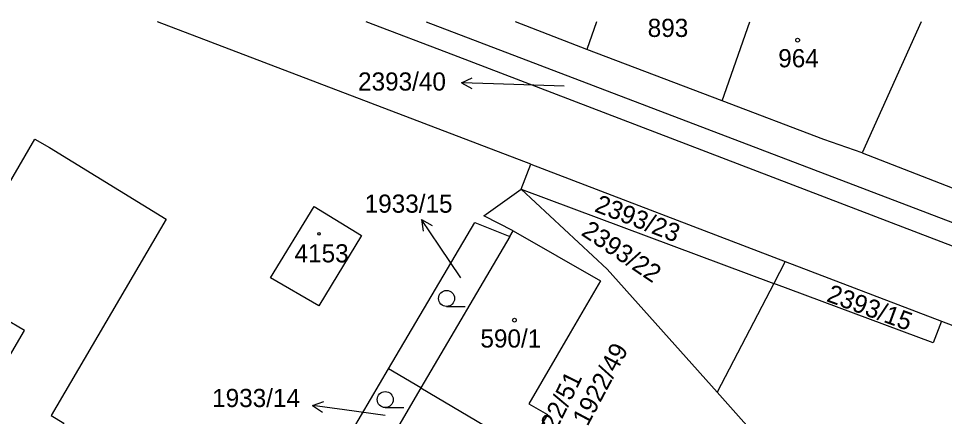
# Model space of a CAD drawing. Extents: x -667048 to -665920, y -1108425 to -1107247.
# Drawn here: x -666872 to -666785.4, y -1107285.9 to -1107248.7 of the extents above; entities that cross this region are included whole.
import ezdxf

# ---------------------------------------------------------------- set-up
doc = ezdxf.new("R2010")
doc.units = 0
for name, color, linetype in [('Default', 7, 'Continuous'), ('Hranice parcel', 7, 'Continuous'), ('Parcelní čísla', 7, 'Continuous'), ('Pop_ PČ_ popisy', 7, 'Continuous'), ('Značky budov', 7, 'Continuous'), ('Značky kultur', 7, 'Continuous')]:
    doc.layers.add(name, color=color, linetype=linetype)

# ---------------------------------------------------------------- blocks, each defined once
blk = doc.blocks.new('3.041')
at = {"layer": 'Default'}
blk.add_line((8, 0), (1758, 0), dxfattribs=at)
blk.add_circle((8, 750), 750, dxfattribs=at)
blk = doc.blocks.new('4.021')
at = {"layer": 'Default'}
blk.add_circle((-7, 1), 175, dxfattribs=at)
blk = doc.blocks.new('10291')
at = {"layer": 'Default'}
for p, q in [((0, 3001), (-500, 2001)), ((0, 1), (0, 3001)), ((0, 3001), (500, 2001))]:
    blk.add_line(p, q, dxfattribs=at)

msp = doc.modelspace()

# ---------------------------------------------------------------- linework, layer by layer
at = {"layer": 'Hranice parcel'}
for points in [[(-666824.13, -1107262.33), (-666859.037, -1107248.984)], [(-666688.05, -1107304.64), (-666689.7, -1107305.15), (-666692.11, -1107304.85), (-666698.12, -1107303.11), (-666714.26, -1107296.9), (-666751.76, -1107282.58), (-666790.4, -1107267.81), (-666831.33, -1107252.12), (-666839.513, -1107248.984)], [(-666833.901, -1107248.984), (-666698.98, -1107300.47), (-666688.05, -1107304.64)], [(-666818.88, -1107251.58), (-666825.552, -1107248.984)], [(-666817.976, -1107248.984), (-666818.88, -1107251.58)], [(-666806.24, -1107256.38), (-666803.631, -1107248.984)], [(-666787.622, -1107248.984), (-666793.14, -1107261.27)], [(-666806.24, -1107256.38), (-666818.88, -1107251.58)], [(-666793.14, -1107261.27), (-666796.71, -1107260.02), (-666806.24, -1107256.38)], [(-666875.51, -1107268.51), (-666870.51, -1107259.98), (-666869.16, -1107260.77), (-666858.24, -1107267.45)], [(-666793.14, -1107261.27), (-666764.11, -1107272.54)], [(-666825.02, -1107264.65), (-666824.13, -1107262.33)], [(-666824.13, -1107262.33), (-666800.32, -1107271.44)], [(-666825.77, -1107268.56), (-666828.51, -1107267.15), (-666825.02, -1107264.65)], [(-666806.68, -1107283.67), (-666816.97, -1107272.13), (-666825.02, -1107264.65)], [(-666825.02, -1107264.65), (-666801.38, -1107273.47)], [(-666839.97, -1107268.98), (-666843.96, -1107275.59), (-666848.47, -1107272.97), (-666844.4, -1107266.28), (-666839.97, -1107268.98)], [(-666858.24, -1107267.45), (-666869, -1107285.85), (-666867.8, -1107286.56), (-666869.39, -1107289.23), (-666870.57, -1107288.53), (-666873.32, -1107293.22)], [(-666837.43, -1107281.48), (-666829.37, -1107267.79), (-666826.08, -1107269.09)], [(-666826.08, -1107269.09), (-666825.77, -1107268.56)], [(-666825.77, -1107268.56), (-666817.61, -1107273.24), (-666820.44, -1107278.11), (-666824.3, -1107284.74), (-666822.57, -1107285.74), (-666824.52, -1107289.09)], [(-666826.08, -1107269.09), (-666834.41, -1107283.26)], [(-666800.32, -1107271.44), (-666801.38, -1107273.47)], [(-666800.32, -1107271.44), (-666785.71, -1107277.02)], [(-666801.38, -1107273.47), (-666806.68, -1107283.67)], [(-666785.71, -1107277.02), (-666786.48, -1107279.03), (-666801.38, -1107273.47)], [(-666874.09, -1107282.3), (-666871.48, -1107277.89), (-666877.21, -1107274.52)], [(-666785.71, -1107277.02), (-666773.74, -1107281.61)], [(-666840.81, -1107287.22), (-666837.43, -1107281.48)], [(-666834.41, -1107283.26), (-666837.43, -1107281.48)], [(-666834.41, -1107283.26), (-666837.79, -1107289.01)], [(-666834.41, -1107283.26), (-666826.25, -1107288.09)], [(-666806.68, -1107283.67), (-666801.66, -1107289.3), (-666798.36, -1107293)]]:
    msp.add_lwpolyline(points, dxfattribs=at)
at = {"layer": 'Pop_ PČ_ popisy'}
for points in [[(-666820.99, -1107255.01), (-666827.62, -1107254.8)], [(-666830.68, -1107272.97), (-666832.66, -1107269.98)], [(-666837.75, -1107285.84), (-666841.56, -1107285.31)]]:
    msp.add_lwpolyline(points, dxfattribs=at)

# ---------------------------------------------------------------- block references
for p, xscale, yscale, rotation in [((-666827.62, -1107254.8), 0.0010000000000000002, 0.001, 88.0000000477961), ((-666832.66, -1107269.98), 0.0010000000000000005, 0.0010000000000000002, 33.99999999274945), ((-666841.56, -1107285.31), 0.001, 0.0009999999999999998, 82.00000005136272)]:
    msp.add_blockref('10291', p, dxfattribs=dict(at, xscale=xscale, yscale=yscale, rotation=rotation))
at = {"layer": 'Značky budov'}
for p, xscale, yscale in [((-666799.16, -1107250.71), 0.0010000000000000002, 0.0010000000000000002), ((-666843.94, -1107268.84), 0.0006700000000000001, 0.0006700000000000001), ((-666825.65, -1107276.92), 0.0010000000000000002, 0.0010000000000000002)]:
    msp.add_blockref('4.021', p, dxfattribs=dict(at, xscale=xscale, yscale=yscale))
at = {"layer": 'Značky kultur', "xscale": 0.0010000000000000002, "yscale": 0.0010000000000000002}
for p in [(-666832.01, -1107275.63), (-666837.75, -1107285.1)]:
    msp.add_blockref('3.041', p, dxfattribs=at)

# ---------------------------------------------------------------- texts
at = {"layer": 'Parcelní čísla'}
for s, p in [('893', (-666813.19, -1107250.41)), ('964', (-666800.98, -1107253.25)), ('2393/40', (-666840.282, -1107255.43)), ('1933/15', (-666839.664, -1107266.86)), ('4153', (-666846.22, -1107271.51)), ('590/1', (-666828.839, -1107279.48)), ('1933/14', (-666853.934, -1107285.05))]:
    msp.add_text(s, height=1.7, dxfattribs=at).set_placement(p)
for s, rotation, p in [('2393/23', 339, (-666818.258, -1107266.714)), ('2393/22', 326, (-666819.499, -1107268.896)), ('2393/15', 340, (-666796.56, -1107275.12)), ('1922/49', 62, (-666818.82, -1107286.919)), ('1922/51', 64, (-666822.874, -1107289.655))]:
    msp.add_text(s, height=1.7, rotation=rotation, dxfattribs=at).set_placement(p)

doc.saveas('drawing.dxf')
